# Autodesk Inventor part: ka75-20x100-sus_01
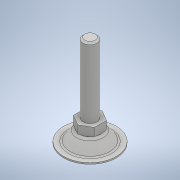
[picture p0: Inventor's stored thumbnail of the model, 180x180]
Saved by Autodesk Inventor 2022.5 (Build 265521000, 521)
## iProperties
Part Number: ka75-20x100-sus_01
Material: 一般
Document SubType Name: Modeling
Designer: ImaoCorp
Density: 1 g/cm^3
Appearance: 既定
Author: ImaoCorp
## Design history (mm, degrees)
feature "ka75-20x100-sus_01"
node "ソリッド1"
